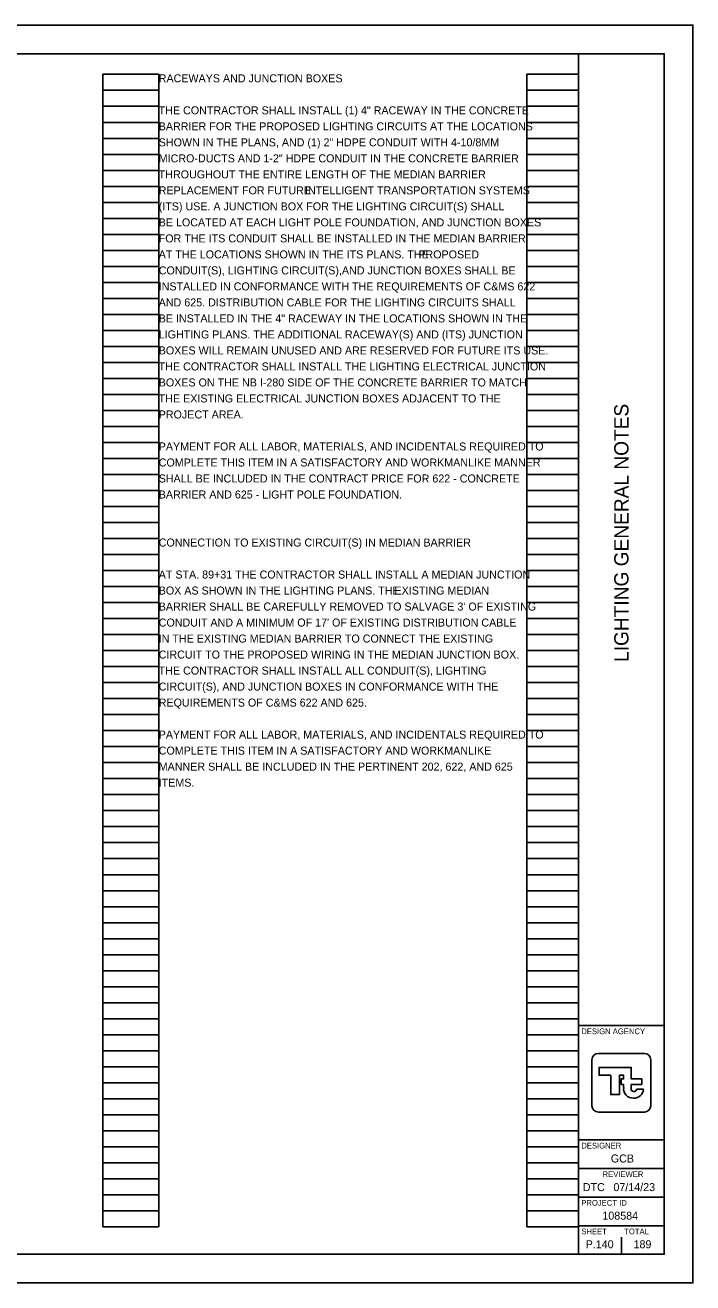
# Model space of a CAD drawing. Extents: x 0 to 34, y 0 to 22.
# Drawn here: x 22.32 to 34, y 0 to 22 of the extents above; entities that cross this region are included whole.
import ezdxf

# ---------------------------------------------------------------- set-up
doc = ezdxf.new("R2010")
doc.units = 0
for name, color, linetype in [('SH_Border', 7, 'Continuous'), ('SH_Cut_Line', 7, 'Continuous'), ('SH_Data', 7, 'Continuous'), ('SH_Text', 7, 'Continuous')]:
    doc.layers.add(name, color=color, linetype=linetype)

msp = doc.modelspace()

# ---------------------------------------------------------------- linework, layer by layer
at = {"layer": 'SH_Border'}
for p, q in [((32, 0.5), (32, 21.5)), ((32, 4.5), (33.5, 4.5)), ((32, 2.5), (33.5, 2.5)), ((32, 2), (33.5, 2)), ((32, 1.5), (33.5, 1.5)), ((32, 1), (33.5, 1))]:
    msp.add_line(p, q, dxfattribs=at)
msp.add_lwpolyline([(1.5, 21.5), (33.5, 21.5), (33.5, 0.5), (1.5, 0.5)], close=True, dxfattribs=at)
at = {"layer": 'SH_Cut_Line'}
msp.add_lwpolyline([(0, 0), (34, 0), (34, 22), (0, 22)], close=True, dxfattribs=at)
at = {"layer": 'SH_Data'}
for p, q in [((23.68, 0.98), (23.68, 21.14)), ((23.68, 21.14), (24.66, 21.14)), ((24.66, 0.98), (24.66, 21.14)), ((31.1, 0.98), (31.1, 21.14)), ((31.1, 21.14), (32, 21.14)), ((32, 0.98), (32, 21.14)), ((23.68, 20.86), (24.66, 20.86)), ((31.1, 20.86), (32, 20.86)), ((23.68, 20.58), (24.66, 20.58)), ((31.1, 20.58), (32, 20.58)), ((23.68, 20.3), (24.66, 20.3)), ((31.1, 20.3), (32, 20.3)), ((23.68, 20.02), (24.66, 20.02)), ((31.1, 20.02), (32, 20.02)), ((23.68, 19.74), (24.66, 19.74)), ((31.1, 19.74), (32, 19.74)), ((23.68, 19.46), (24.66, 19.46)), ((31.1, 19.46), (32, 19.46)), ((23.68, 19.18), (24.66, 19.18)), ((31.1, 19.18), (32, 19.18)), ((23.68, 18.9), (24.66, 18.9)), ((31.1, 18.9), (32, 18.9)), ((23.68, 18.62), (24.66, 18.62)), ((31.1, 18.62), (32, 18.62)), ((23.68, 18.34), (24.66, 18.34)), ((31.1, 18.34), (32, 18.34)), ((23.68, 18.06), (24.66, 18.06)), ((31.1, 18.06), (32, 18.06)), ((23.68, 17.78), (24.66, 17.78)), ((31.1, 17.78), (32, 17.78)), ((23.68, 17.5), (24.66, 17.5)), ((31.1, 17.5), (32, 17.5)), ((23.68, 17.22), (24.66, 17.22)), ((31.1, 17.22), (32, 17.22)), ((23.68, 16.94), (24.66, 16.94)), ((31.1, 16.94), (32, 16.94)), ((23.68, 16.66), (24.66, 16.66)), ((31.1, 16.66), (32, 16.66)), ((23.68, 16.38), (24.66, 16.38)), ((31.1, 16.38), (32, 16.38)), ((23.68, 16.1), (24.66, 16.1)), ((31.1, 16.1), (32, 16.1)), ((23.68, 15.82), (24.66, 15.82)), ((31.1, 15.82), (32, 15.82)), ((23.68, 15.54), (24.66, 15.54)), ((31.1, 15.54), (32, 15.54)), ((23.68, 15.26), (24.66, 15.26)), ((31.1, 15.26), (32, 15.26)), ((23.68, 14.98), (24.66, 14.98)), ((31.1, 14.98), (32, 14.98)), ((23.68, 14.7), (24.66, 14.7)), ((31.1, 14.7), (32, 14.7)), ((23.68, 14.42), (24.66, 14.42)), ((31.1, 14.42), (32, 14.42)), ((23.68, 14.14), (24.66, 14.14)), ((31.1, 14.14), (32, 14.14)), ((23.68, 13.86), (24.66, 13.86)), ((31.1, 13.86), (32, 13.86)), ((23.68, 13.58), (24.66, 13.58)), ((31.1, 13.58), (32, 13.58)), ((23.68, 13.3), (24.66, 13.3)), ((31.1, 13.3), (32, 13.3)), ((23.68, 13.02), (24.66, 13.02)), ((31.1, 13.02), (32, 13.02)), ((23.68, 12.74), (24.66, 12.74)), ((31.1, 12.74), (32, 12.74)), ((23.68, 12.46), (24.66, 12.46)), ((31.1, 12.46), (32, 12.46)), ((23.68, 12.18), (24.66, 12.18)), ((31.1, 12.18), (32, 12.18)), ((23.68, 11.9), (24.66, 11.9)), ((31.1, 11.9), (32, 11.9)), ((23.68, 11.62), (24.66, 11.62)), ((31.1, 11.62), (32, 11.62)), ((23.68, 11.34), (24.66, 11.34)), ((31.1, 11.34), (32, 11.34)), ((23.68, 11.06), (24.66, 11.06)), ((31.1, 11.06), (32, 11.06)), ((23.68, 10.78), (24.66, 10.78)), ((31.1, 10.78), (32, 10.78)), ((23.68, 10.5), (24.66, 10.5)), ((31.1, 10.5), (32, 10.5)), ((23.68, 10.22), (24.66, 10.22)), ((31.1, 10.22), (32, 10.22)), ((23.68, 9.94), (24.66, 9.94)), ((31.1, 9.94), (32, 9.94)), ((23.68, 9.66), (24.66, 9.66)), ((31.1, 9.66), (32, 9.66)), ((23.68, 9.38), (24.66, 9.38)), ((31.1, 9.38), (32, 9.38)), ((23.68, 9.1), (24.66, 9.1)), ((31.1, 9.1), (32, 9.1)), ((23.68, 8.82), (24.66, 8.82)), ((31.1, 8.82), (32, 8.82)), ((23.68, 8.54), (24.66, 8.54)), ((31.1, 8.54), (32, 8.54)), ((23.68, 8.26), (24.66, 8.26)), ((31.1, 8.26), (32, 8.26)), ((23.68, 7.98), (24.66, 7.98)), ((31.1, 7.98), (32, 7.98)), ((23.68, 7.7), (24.66, 7.7)), ((31.1, 7.7), (32, 7.7)), ((23.68, 7.42), (24.66, 7.42)), ((31.1, 7.42), (32, 7.42)), ((23.68, 7.14), (24.66, 7.14)), ((31.1, 7.14), (32, 7.14)), ((23.68, 6.86), (24.66, 6.86)), ((31.1, 6.86), (32, 6.86)), ((23.68, 6.58), (24.66, 6.58)), ((31.1, 6.58), (32, 6.58)), ((23.68, 6.3), (24.66, 6.3)), ((31.1, 6.3), (32, 6.3)), ((23.68, 6.02), (24.66, 6.02)), ((31.1, 6.02), (32, 6.02)), ((23.68, 5.74), (24.66, 5.74)), ((31.1, 5.74), (32, 5.74)), ((23.68, 5.46), (24.66, 5.46)), ((31.1, 5.46), (32, 5.46)), ((23.68, 5.18), (24.66, 5.18)), ((31.1, 5.18), (32, 5.18)), ((23.68, 4.9), (24.66, 4.9)), ((31.1, 4.9), (32, 4.9)), ((23.68, 4.62), (24.66, 4.62)), ((31.1, 4.62), (32, 4.62)), ((23.68, 4.34), (24.66, 4.34)), ((31.1, 4.34), (32, 4.34)), ((23.68, 4.06), (24.66, 4.06)), ((31.1, 4.06), (32, 4.06)), ((23.68, 3.78), (24.66, 3.78)), ((31.1, 3.78), (32, 3.78)), ((23.68, 3.5), (24.66, 3.5)), ((31.1, 3.5), (32, 3.5)), ((32.75, 3.5), (32.75, 3.5)), ((32.791, 3.415), (32.791, 3.415)), ((33.136, 3.385), (33.015, 3.385)), ((23.68, 3.22), (24.66, 3.22)), ((31.1, 3.22), (32, 3.22)), ((23.68, 2.94), (24.66, 2.94)), ((31.1, 2.94), (32, 2.94)), ((23.68, 2.66), (24.66, 2.66)), ((31.1, 2.66), (32, 2.66)), ((23.68, 2.38), (24.66, 2.38)), ((31.1, 2.38), (32, 2.38)), ((23.68, 2.1), (24.66, 2.1)), ((31.1, 2.1), (32, 2.1)), ((23.68, 1.82), (24.66, 1.82)), ((31.1, 1.82), (32, 1.82)), ((23.68, 1.54), (24.66, 1.54)), ((31.1, 1.54), (32, 1.54)), ((23.68, 1.26), (24.66, 1.26)), ((31.1, 1.26), (32, 1.26)), ((23.68, 0.98), (24.66, 0.98)), ((31.1, 0.98), (32, 0.98)), ((32.375, 0.675), (32.375, 0.675)), ((32.75, 0.5), (32.75, 0.8))]:
    msp.add_line(p, q, dxfattribs=at)
for points in [[(32.348, 4.014), (33.152, 4.014)], [(32.236, 3.099), (32.236, 3.901)], [(32.922, 3.399), (32.922, 3.47), (33.107, 3.47), (33.107, 3.568), (32.922, 3.568), (32.922, 3.768), (32.361, 3.768), (32.361, 3.632), (32.566, 3.632), (32.566, 3.294), (32.715, 3.294), (32.715, 3.63), (32.79, 3.63), (32.79, 3.568), (32.748, 3.568), (32.748, 3.47), (32.79, 3.47), (32.79, 3.415), (32.791, 3.415)], [(33.264, 3.901), (33.264, 3.099)], [(33.152, 2.986), (32.348, 2.986)]]:
    msp.add_lwpolyline(points, dxfattribs=at)
for centre, radius, start, end in [((32.348, 3.901), 0.113, 90, 180), ((33.152, 3.901), 0.113, 360, 90), ((32.949, 3.392), 0.16, 171.8856, 274.8323), ((32.968, 3.392), 0.0473, 171.8856, 350.9243), ((32.976, 3.392), 0.16, 265.1677, 357.3201), ((32.348, 3.099), 0.113, 180, 270), ((33.152, 3.099), 0.113, 270, 360)]:
    msp.add_arc(centre, radius, start, end, dxfattribs=at)

# ---------------------------------------------------------------- texts
msp.add_text('LIGHTING GENERAL NOTES', height=0.25, rotation=90, dxfattribs=at).set_placement((32.875, 10.862))
for s, height, p in [('DESIGN AGENCY', 0.1, (32.05, 4.35)), ('DESIGNER', 0.1, (32.05, 2.35)), ('GCB', 0.14, (32.566, 2.105)), ('REVIEWER', 0.1, (32.422, 1.85)), ('DTC', 0.14, (32.076, 1.605)), ('07/14/23', 0.14, (32.611, 1.605)), ('PROJECT ID', 0.1, (32.05, 1.35)), ('108584', 0.14, (32.418, 1.105)), ('SHEET', 0.1, (32.05, 0.85)), ('TOTAL', 0.1, (32.8, 0.85)), ('P.140', 0.14, (32.126, 0.605)), ('189', 0.14, (32.963, 0.605))]:
    msp.add_text(s, height=height, dxfattribs=at).set_placement(p)
at = {"layer": 'SH_Text'}
for s, p in [('RACEWAYS AND JUNCTION BOXES', (24.66, 21)), ('THE CONTRACTOR SHALL INSTALL (1) 4" RACEWAY IN THE CONCRETE ', (24.66, 20.44)), ('BARRIER FOR THE PROPOSED LIGHTING CIRCUITS AT THE LOCATIONS ', (24.66, 20.16)), ('SHOWN IN THE PLANS, AND (1) 2" HDPE CONDUIT WITH 4-10/8MM', (24.66, 19.88)), ('MICRO-DUCTS AND 1-2" HDPE CONDUIT IN THE CONCRETE BARRIER ', (24.66, 19.6)), ('THROUGHOUT THE ENTIRE LENGTH OF THE MEDIAN BARRIER ', (24.66, 19.32)), ('REPLACEMENT FOR FUTURE ', (24.66, 19.04)), ('INTELLIGENT TRANSPORTATION SYSTEMS ', (27.218, 19.04)), ('(ITS) USE. A JUNCTION BOX FOR THE LIGHTING CIRCUIT(S) SHALL ', (24.66, 18.76)), ('BE LOCATED AT EACH LIGHT POLE FOUNDATION, AND JUNCTION BOXES ', (24.66, 18.48)), ('FOR THE ITS CONDUIT SHALL BE INSTALLED IN THE MEDIAN BARRIER ', (24.66, 18.2)), ('AT THE LOCATIONS SHOWN IN THE ITS PLANS. THE', (24.66, 17.92)), (' PROPOSED ', (29.148, 17.92)), ('CONDUIT(S), LIGHTING CIRCUIT(S),AND JUNCTION BOXES SHALL BE ', (24.66, 17.64)), ('INSTALLED IN CONFORMANCE WITH THE REQUIREMENTS OF C&MS 622 ', (24.66, 17.36)), ('AND 625. DISTRIBUTION CABLE FOR THE LIGHTING CIRCUITS SHALL ', (24.66, 17.08)), ('BE INSTALLED IN THE 4" RACEWAY IN THE LOCATIONS SHOWN IN THE ', (24.66, 16.8)), ('LIGHTING PLANS. THE ADDITIONAL RACEWAY(S) AND (ITS) JUNCTION ', (24.66, 16.52)), ('BOXES WILL REMAIN UNUSED AND ARE RESERVED FOR FUTURE ITS USE. ', (24.66, 16.24)), ('THE CONTRACTOR SHALL INSTALL THE LIGHTING ELECTRICAL JUNCTION ', (24.66, 15.96)), ('BOXES ON THE NB I-280 SIDE OF THE CONCRETE BARRIER TO MATCH ', (24.66, 15.68)), ('THE EXISTING ELECTRICAL JUNCTION BOXES ADJACENT TO THE ', (24.66, 15.4)), ('PROJECT AREA.', (24.66, 15.12)), ('PAYMENT FOR ALL LABOR, MATERIALS, AND INCIDENTALS REQUIRED TO ', (24.66, 14.56)), ('COMPLETE THIS ITEM IN A SATISFACTORY AND WORKMANLIKE MANNER ', (24.66, 14.28)), ('SHALL BE INCLUDED IN THE CONTRACT PRICE FOR 622 - CONCRETE ', (24.66, 14)), ('BARRIER AND 625 - LIGHT POLE FOUNDATION.', (24.66, 13.72)), ('CONNECTION TO EXISTING CIRCUIT(S) IN MEDIAN BARRIER', (24.66, 12.88)), ('AT STA. 89+31 THE CONTRACTOR SHALL INSTALL A MEDIAN JUNCTION', (24.66, 12.32)), ('BOX AS SHOWN IN THE LIGHTING PLANS. THE', (24.66, 12.04)), (' EXISTING MEDIAN ', (28.731, 12.04)), ("BARRIER SHALL BE CAREFULLY REMOVED TO SALVAGE 3' OF EXISTING", (24.66, 11.76)), ("CONDUIT AND A MINIMUM OF 17' OF EXISTING DISTRIBUTION CABLE ", (24.66, 11.48)), ('IN THE EXISTING MEDIAN BARRIER TO CONNECT THE EXISTING ', (24.66, 11.2)), ('CIRCUIT TO THE PROPOSED WIRING IN THE MEDIAN JUNCTION BOX. ', (24.66, 10.92)), ('THE CONTRACTOR SHALL INSTALL ALL CONDUIT(S), LIGHTING ', (24.66, 10.64)), ('CIRCUIT(S), AND JUNCTION BOXES IN CONFORMANCE WITH THE ', (24.66, 10.36)), ('REQUIREMENTS OF C&MS 622 AND 625.', (24.66, 10.08)), ('PAYMENT FOR ALL LABOR, MATERIALS, AND INCIDENTALS REQUIRED TO ', (24.66, 9.52)), ('COMPLETE THIS ITEM IN A SATISFACTORY AND WORKMANLIKE ', (24.66, 9.24)), ('MANNER SHALL BE INCLUDED IN THE PERTINENT 202, 622, AND 625 ', (24.66, 8.96)), ('ITEMS.', (24.66, 8.68))]:
    msp.add_text(s, height=0.14, dxfattribs=at).set_placement(p)

doc.saveas('drawing.dxf')
